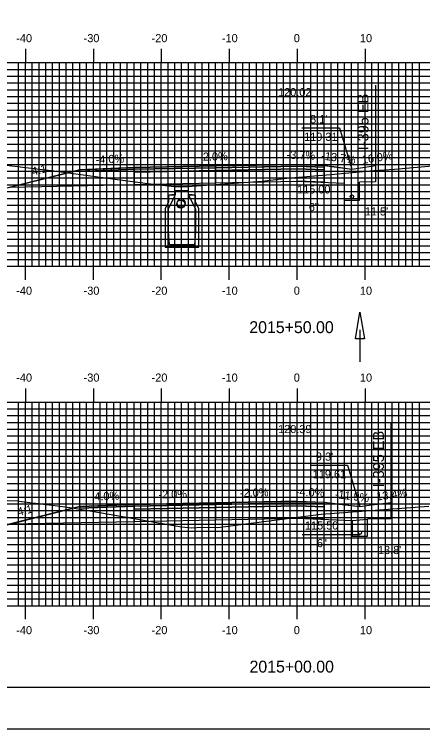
# Model space of a CAD drawing. Extents: x 854681 to 855024, y 366605 to 366825.
# Drawn here: x 854804.9 to 854865.1, y 366604.9 to 366710.2 of the extents above; entities that cross this region are included whole.
import ezdxf

# ---------------------------------------------------------------- set-up
doc = ezdxf.new("R2010")
doc.units = 0
for name, color, linetype in [('ANNOTATION', 7, 'Continuous'), ('BORDER', 7, 'Continuous'), ('D_Drainage_Ditch_Line', 7, 'Continuous'), ('D_Roadway_Centerline', 7, 'Continuous'), ('D_Roadway_Centerline_Text', 7, 'Continuous'), ('D_Roadway_Edge_Shoulder', 7, 'Continuous'), ('D_Roadway_Edge_TW', 7, 'Continuous'), ('D_Roadway_Pavement', 7, 'Continuous'), ('D_Roadway_SlopeLines', 7, 'Continuous'), ('D_Roadway_SubGrade', 7, 'Continuous'), ('D_Text_Standard', 7, 'Continuous'), ('H_V ANNOTATION', 7, 'Continuous'), ('JUNK', 7, 'Continuous'), ('MAJOR', 7, 'Continuous'), ('MINOR', 7, 'Continuous'), ('PDRAIN', 7, 'Continuous'), ('PLOT BOUNDARY', 7, 'Continuous'), ('S_Drainage_CB', 7, 'Continuous'), ('S_Drainage_Invert', 7, 'Continuous'), ('S_Roadway_Centerline', 7, 'Continuous')]:
    doc.layers.add(name, color=color, linetype=linetype)

msp = doc.modelspace()

# ---------------------------------------------------------------- linework, layer by layer
at = {"layer": 'ANNOTATION'}
for points in [[(854847.23, 366693.45), (854852.81, 366693.45), (854854.63, 366687.37)], [(854848.61, 366643.75), (854853.99, 366643.75), (854855.81, 366637.66)]]:
    msp.add_lwpolyline(points, dxfattribs=at)
at = {"layer": 'BORDER'}
msp.add_lwpolyline([(854696.96, 366611.06), (855016.96, 366611.06), (855016.96, 366821.06), (854696.96, 366821.06)], close=True, dxfattribs=at)
at = {"layer": 'D_Drainage_Ditch_Line'}
msp.add_line((854855.81, 366663.69), (854855.81, 366658.99), dxfattribs=at)
msp.add_lwpolyline([(854856.46, 366662.37), (854855.15, 366662.37), (854855.81, 366666.31)], close=True, dxfattribs=at)
at = {"layer": 'D_Roadway_Centerline'}
for p, q in [((854846.56, 366685.57), (854853.5, 366685.32)), ((854858.08, 366685.48), (854855.75, 366685.43)), ((854846.56, 366635.95), (854854.68, 366635.62))]:
    msp.add_line(p, q, dxfattribs=at)
for points in [[(854751.25, 366686.43), (854751.26, 366686.43), (854800.38, 366683.73), (854802.76, 366684.32), (854803.66, 366684.55), (854810.24, 366686.2), (854814.56, 366687.27), (854816.02, 366687.33), (854822.55, 366687.59), (854822.56, 366687.59), (854822.56, 366687.59), (854834.56, 366687.83), (854846.56, 366688.07), (854848.89, 366687.99), (854850.56, 366687.92), (854851.62, 366687.78), (854854.63, 366687.37)], [(854850.56, 366687.92), (854854.63, 366687.37)], [(854854.63, 366687.37), (854855.6, 366687.52), (854858.08, 366687.92)], [(854759.48, 366637.54), (854759.49, 366637.54), (854800.38, 366634.1), (854803.66, 366634.92), (854803.66, 366634.92), (854814.56, 366637.65), (854814.56, 366637.65), (854818.67, 366637.81), (854822.56, 366637.97), (854834.55, 366638.21), (854834.56, 366638.21), (854846.55, 366638.45), (854846.56, 366638.45), (854850.56, 366638.29), (854852.3, 366638.08), (854855.81, 366637.66)], [(854850.56, 366638.29), (854855.81, 366637.66)], [(854855.81, 366637.66), (854857.18, 366637.85), (854860.36, 366638.27)], [(854860.36, 366635.85), (854856.93, 366635.78)]]:
    msp.add_lwpolyline(points, dxfattribs=at)
at = {"layer": 'D_Roadway_Edge_Shoulder'}
for points in [[(854846.56, 366688.07), (854850.56, 366687.92), (854850.56, 366687.67), (854846.56, 366687.82)], [(854822.56, 366687.59), (854814.56, 366687.27), (854814.56, 366687.02), (854822.56, 366687.34)], [(854846.56, 366638.45), (854850.56, 366638.29), (854850.56, 366638.04), (854846.56, 366638.2)], [(854822.56, 366637.97), (854814.56, 366637.65), (854814.56, 366637.4), (854822.56, 366637.72)]]:
    msp.add_lwpolyline(points, close=True, dxfattribs=at)
at = {"layer": 'D_Roadway_Edge_TW'}
for points in [[(854834.56, 366687.83), (854822.56, 366687.59), (854822.56, 366687.34), (854834.56, 366687.58)], [(854846.56, 366688.07), (854834.56, 366687.83), (854834.56, 366687.58), (854846.56, 366687.82)], [(854846.56, 366638.45), (854834.56, 366638.21), (854834.56, 366637.96), (854846.56, 366638.2)], [(854834.56, 366638.21), (854822.56, 366637.97), (854822.56, 366637.72), (854834.56, 366637.96)]]:
    msp.add_lwpolyline(points, close=True, dxfattribs=at)
at = {"layer": 'D_Roadway_Pavement'}
for points in [[(854846.56, 366687.82), (854834.56, 366687.58), (854834.56, 366687.17), (854846.56, 366687.41)], [(854846.56, 366687.82), (854850.56, 366687.67), (854850.56, 366687.26), (854846.56, 366687.41)], [(854834.56, 366687.58), (854822.56, 366687.34), (854822.56, 366686.93), (854834.56, 366687.17)], [(854834.56, 366637.96), (854822.56, 366637.72), (854822.56, 366637.3), (854834.56, 366637.54)], [(854846.56, 366638.2), (854834.56, 366637.96), (854834.56, 366637.54), (854846.56, 366637.78)], [(854846.56, 366638.2), (854850.56, 366638.04), (854850.56, 366637.62), (854846.56, 366637.78)]]:
    msp.add_lwpolyline(points, close=True, dxfattribs=at)
for points in [[(854822.56, 366687.34), (854822.56, 366686.93)], [(854822.56, 366687.34), (854822.56, 366686.93)], [(854834.56, 366687.58), (854834.56, 366687.17)], [(854822.56, 366637.72), (854822.56, 366637.3)], [(854822.56, 366637.72), (854822.56, 366637.3)], [(854834.56, 366637.96), (854834.56, 366637.54)]]:
    msp.add_lwpolyline(points, dxfattribs=at)
at = {"layer": 'D_Roadway_SlopeLines'}
for p, q in [((854814.56, 366687.27), (854800.38, 366683.73)), ((854814.56, 366637.65), (854800.38, 366634.1))]:
    msp.add_line(p, q, dxfattribs=at)
at = {"layer": 'D_Roadway_SubGrade'}
for p, q in [((854858.08, 366699.73), (854858.08, 366685.48)), ((854860.36, 366650.08), (854860.36, 366635.85))]:
    msp.add_line(p, q, dxfattribs=at)
for points in [[(854846.56, 366687.41), (854850.56, 366687.26), (854850.56, 366687.67), (854850.56, 366687.92), (854850.56, 366685.42), (854846.56, 366685.57)], [(854822.56, 366686.93), (854822.56, 366687.34), (854814.56, 366687.02), (854814.56, 366687.27), (854804.38, 366684.73), (854822.56, 366685.09)], [(854834.56, 366687.17), (854822.56, 366686.93), (854822.56, 366685.09), (854834.56, 366685.33)], [(854846.56, 366687.41), (854834.56, 366687.17), (854834.56, 366685.33), (854846.56, 366685.57)], [(854822.56, 366637.3), (854822.56, 366637.72), (854814.56, 366637.4), (854814.56, 366637.65), (854804.38, 366635.1), (854822.56, 366635.47)], [(854834.56, 366637.54), (854822.56, 366637.3), (854822.56, 366635.47), (854834.56, 366635.71)], [(854846.56, 366637.78), (854834.56, 366637.54), (854834.56, 366635.71), (854846.56, 366635.95)], [(854846.56, 366637.78), (854850.56, 366637.62), (854850.56, 366638.04), (854850.56, 366638.29), (854850.56, 366635.79), (854846.56, 366635.95)]]:
    msp.add_lwpolyline(points, close=True, dxfattribs=at)
at = {"layer": 'JUNK'}
msp.add_line((854854.68, 366635.62), (854856.93, 366635.78), dxfattribs=at)
at = {"layer": 'MAJOR'}
for p, q in [((854806.56, 366705.06), (854806.56, 366703.06)), ((854816.56, 366705.06), (854816.56, 366703.06)), ((854826.56, 366705.06), (854826.56, 366703.06)), ((854836.56, 366705.06), (854836.56, 366703.06)), ((854846.56, 366705.06), (854846.56, 366703.06)), ((854856.56, 366705.06), (854856.56, 366703.06)), ((854706.56, 366703.06), (854986.56, 366703.06)), ((854706.56, 366703.06), (854986.56, 366703.06)), ((854806.56, 366673.06), (854806.56, 366703.06)), ((854816.56, 366673.06), (854816.56, 366703.06)), ((854826.56, 366673.06), (854826.56, 366703.06)), ((854836.56, 366673.06), (854836.56, 366703.06)), ((854846.56, 366673.06), (854846.56, 366703.06)), ((854856.56, 366673.06), (854856.56, 366703.06)), ((854706.56, 366698.06), (854986.56, 366698.06)), ((854706.56, 366693.06), (854986.56, 366693.06)), ((854706.56, 366688.06), (854986.56, 366688.06)), ((854706.56, 366683.06), (854986.56, 366683.06)), ((854706.56, 366678.06), (854986.56, 366678.06)), ((854706.56, 366673.06), (854986.56, 366673.06)), ((854706.56, 366673.06), (854986.56, 366673.06)), ((854806.56, 366671.05), (854806.56, 366673.06)), ((854816.56, 366671.05), (854816.56, 366673.06)), ((854826.56, 366671.05), (854826.56, 366673.06)), ((854836.56, 366671.05), (854836.56, 366673.06)), ((854846.56, 366671.05), (854846.56, 366673.06)), ((854856.56, 366671.05), (854856.56, 366673.06)), ((854806.56, 366655.06), (854806.56, 366653.06)), ((854816.56, 366655.06), (854816.56, 366653.06)), ((854826.56, 366655.06), (854826.56, 366653.06)), ((854836.56, 366655.06), (854836.56, 366653.06)), ((854846.56, 366655.06), (854846.56, 366653.06)), ((854856.56, 366655.06), (854856.56, 366653.06)), ((854706.56, 366653.06), (854986.56, 366653.06)), ((854706.56, 366653.06), (854986.56, 366653.06)), ((854806.56, 366623.06), (854806.56, 366653.06)), ((854816.56, 366623.06), (854816.56, 366653.06)), ((854826.56, 366623.06), (854826.56, 366653.06)), ((854836.56, 366623.06), (854836.56, 366653.06)), ((854846.56, 366623.06), (854846.56, 366653.06)), ((854856.56, 366623.06), (854856.56, 366653.06)), ((854706.56, 366648.06), (854986.56, 366648.06)), ((854706.56, 366643.06), (854986.56, 366643.06)), ((854706.56, 366638.06), (854986.56, 366638.06)), ((854706.56, 366633.06), (854986.56, 366633.06)), ((854706.56, 366628.06), (854986.56, 366628.06)), ((854706.56, 366623.06), (854986.56, 366623.06)), ((854706.56, 366623.06), (854986.56, 366623.06)), ((854806.56, 366621.05), (854806.56, 366623.06)), ((854816.56, 366621.05), (854816.56, 366623.06)), ((854826.56, 366621.05), (854826.56, 366623.06)), ((854836.56, 366621.05), (854836.56, 366623.06)), ((854846.56, 366621.05), (854846.56, 366623.06)), ((854856.56, 366621.05), (854856.56, 366623.06))]:
    msp.add_line(p, q, dxfattribs=at)
at = {"layer": 'MINOR'}
for p, q in [((854805.56, 366673.06), (854805.56, 366703.06)), ((854807.56, 366673.06), (854807.56, 366703.06)), ((854808.56, 366673.06), (854808.56, 366703.06)), ((854809.56, 366673.06), (854809.56, 366703.06)), ((854810.56, 366673.06), (854810.56, 366703.06)), ((854811.56, 366673.06), (854811.56, 366703.06)), ((854812.56, 366673.06), (854812.56, 366703.06)), ((854813.56, 366673.06), (854813.56, 366703.06)), ((854814.56, 366673.06), (854814.56, 366703.06)), ((854815.56, 366673.06), (854815.56, 366703.06)), ((854817.56, 366673.06), (854817.56, 366703.06)), ((854818.56, 366673.06), (854818.56, 366703.06)), ((854819.56, 366673.06), (854819.56, 366703.06)), ((854820.56, 366673.06), (854820.56, 366703.06)), ((854821.56, 366673.06), (854821.56, 366703.06)), ((854822.56, 366673.06), (854822.56, 366703.06)), ((854823.56, 366673.06), (854823.56, 366703.06)), ((854824.56, 366673.06), (854824.56, 366703.06)), ((854825.56, 366673.06), (854825.56, 366703.06)), ((854827.56, 366673.06), (854827.56, 366703.06)), ((854828.56, 366673.06), (854828.56, 366703.06)), ((854829.56, 366673.06), (854829.56, 366703.06)), ((854830.56, 366673.06), (854830.56, 366703.06)), ((854831.56, 366673.06), (854831.56, 366703.06)), ((854832.56, 366673.06), (854832.56, 366703.06)), ((854833.56, 366673.06), (854833.56, 366703.06)), ((854834.56, 366673.06), (854834.56, 366703.06)), ((854835.56, 366673.06), (854835.56, 366703.06)), ((854837.56, 366673.06), (854837.56, 366703.06)), ((854838.56, 366673.06), (854838.56, 366703.06)), ((854839.56, 366673.06), (854839.56, 366703.06)), ((854840.56, 366673.06), (854840.56, 366703.06)), ((854841.56, 366673.06), (854841.56, 366703.06)), ((854842.56, 366673.06), (854842.56, 366703.06)), ((854843.56, 366673.06), (854843.56, 366703.06)), ((854844.56, 366673.06), (854844.56, 366703.06)), ((854845.56, 366673.06), (854845.56, 366703.06)), ((854847.56, 366673.06), (854847.56, 366703.06)), ((854848.56, 366673.06), (854848.56, 366703.06)), ((854849.56, 366673.06), (854849.56, 366703.06)), ((854850.56, 366673.06), (854850.56, 366703.06)), ((854851.56, 366673.06), (854851.56, 366703.06)), ((854852.56, 366673.06), (854852.56, 366703.06)), ((854853.56, 366673.06), (854853.56, 366703.06)), ((854854.56, 366673.06), (854854.56, 366703.06)), ((854855.56, 366673.06), (854855.56, 366703.06)), ((854857.56, 366673.06), (854857.56, 366703.06)), ((854858.56, 366673.06), (854858.56, 366703.06)), ((854859.56, 366673.06), (854859.56, 366703.06)), ((854860.56, 366673.06), (854860.56, 366703.06)), ((854861.56, 366673.06), (854861.56, 366703.06)), ((854862.56, 366673.06), (854862.56, 366703.06)), ((854863.56, 366673.06), (854863.56, 366703.06)), ((854864.56, 366673.06), (854864.56, 366703.06)), ((854706.56, 366702.06), (854986.56, 366702.06)), ((854706.56, 366701.06), (854986.56, 366701.06)), ((854706.56, 366700.06), (854986.56, 366700.06)), ((854706.56, 366699.06), (854986.56, 366699.06)), ((854706.56, 366697.06), (854986.56, 366697.06)), ((854706.56, 366696.06), (854986.56, 366696.06)), ((854706.56, 366695.06), (854986.56, 366695.06)), ((854706.56, 366694.06), (854986.56, 366694.06)), ((854706.56, 366692.06), (854986.56, 366692.06)), ((854706.56, 366691.06), (854986.56, 366691.06)), ((854706.56, 366690.06), (854986.56, 366690.06)), ((854706.56, 366689.06), (854986.56, 366689.06)), ((854706.56, 366687.06), (854986.56, 366687.06)), ((854706.56, 366686.06), (854986.56, 366686.06)), ((854706.56, 366685.06), (854986.56, 366685.06)), ((854706.56, 366684.06), (854986.56, 366684.06)), ((854706.56, 366682.06), (854986.56, 366682.06)), ((854706.56, 366681.06), (854986.56, 366681.06)), ((854706.56, 366680.06), (854986.56, 366680.06)), ((854706.56, 366679.06), (854986.56, 366679.06)), ((854706.56, 366677.06), (854986.56, 366677.06)), ((854706.56, 366676.06), (854986.56, 366676.06)), ((854706.56, 366675.06), (854986.56, 366675.06)), ((854706.56, 366674.06), (854986.56, 366674.06)), ((854805.56, 366623.06), (854805.56, 366653.06)), ((854807.56, 366623.06), (854807.56, 366653.06)), ((854808.56, 366623.06), (854808.56, 366653.06)), ((854809.56, 366623.06), (854809.56, 366653.06)), ((854810.56, 366623.06), (854810.56, 366653.06)), ((854811.56, 366623.06), (854811.56, 366653.06)), ((854812.56, 366623.06), (854812.56, 366653.06)), ((854813.56, 366623.06), (854813.56, 366653.06)), ((854814.56, 366623.06), (854814.56, 366653.06)), ((854815.56, 366623.06), (854815.56, 366653.06)), ((854817.56, 366623.06), (854817.56, 366653.06)), ((854818.56, 366623.06), (854818.56, 366653.06)), ((854819.56, 366623.06), (854819.56, 366653.06)), ((854820.56, 366623.06), (854820.56, 366653.06)), ((854821.56, 366623.06), (854821.56, 366653.06)), ((854822.56, 366623.06), (854822.56, 366653.06)), ((854823.56, 366623.06), (854823.56, 366653.06)), ((854824.56, 366623.06), (854824.56, 366653.06)), ((854825.56, 366623.06), (854825.56, 366653.06)), ((854827.56, 366623.06), (854827.56, 366653.06)), ((854828.56, 366623.06), (854828.56, 366653.06)), ((854829.56, 366623.06), (854829.56, 366653.06)), ((854830.56, 366623.06), (854830.56, 366653.06)), ((854831.56, 366623.06), (854831.56, 366653.06)), ((854832.56, 366623.06), (854832.56, 366653.06)), ((854833.56, 366623.06), (854833.56, 366653.06)), ((854834.56, 366623.06), (854834.56, 366653.06)), ((854835.56, 366623.06), (854835.56, 366653.06)), ((854837.56, 366623.06), (854837.56, 366653.06)), ((854838.56, 366623.06), (854838.56, 366653.06)), ((854839.56, 366623.06), (854839.56, 366653.06)), ((854840.56, 366623.06), (854840.56, 366653.06)), ((854841.56, 366623.06), (854841.56, 366653.06)), ((854842.56, 366623.06), (854842.56, 366653.06)), ((854843.56, 366623.06), (854843.56, 366653.06)), ((854844.56, 366623.06), (854844.56, 366653.06)), ((854845.56, 366623.06), (854845.56, 366653.06)), ((854847.56, 366623.06), (854847.56, 366653.06)), ((854848.56, 366623.06), (854848.56, 366653.06)), ((854849.56, 366623.06), (854849.56, 366653.06)), ((854850.56, 366623.06), (854850.56, 366653.06)), ((854851.56, 366623.06), (854851.56, 366653.06)), ((854852.56, 366623.06), (854852.56, 366653.06)), ((854853.56, 366623.06), (854853.56, 366653.06)), ((854854.56, 366623.06), (854854.56, 366653.06)), ((854855.56, 366623.06), (854855.56, 366653.06)), ((854857.56, 366623.06), (854857.56, 366653.06)), ((854858.56, 366623.06), (854858.56, 366653.06)), ((854859.56, 366623.06), (854859.56, 366653.06)), ((854860.56, 366623.06), (854860.56, 366653.06)), ((854861.56, 366623.06), (854861.56, 366653.06)), ((854862.56, 366623.06), (854862.56, 366653.06)), ((854863.56, 366623.06), (854863.56, 366653.06)), ((854864.56, 366623.06), (854864.56, 366653.06)), ((854706.56, 366652.06), (854986.56, 366652.06)), ((854706.56, 366651.06), (854986.56, 366651.06)), ((854706.56, 366650.06), (854986.56, 366650.06)), ((854706.56, 366649.06), (854986.56, 366649.06)), ((854706.56, 366647.06), (854986.56, 366647.06)), ((854706.56, 366646.06), (854986.56, 366646.06)), ((854706.56, 366645.06), (854986.56, 366645.06)), ((854706.56, 366644.06), (854986.56, 366644.06)), ((854706.56, 366642.06), (854986.56, 366642.06)), ((854706.56, 366641.06), (854986.56, 366641.06)), ((854706.56, 366640.06), (854986.56, 366640.06)), ((854706.56, 366639.06), (854986.56, 366639.06)), ((854706.56, 366637.06), (854986.56, 366637.06)), ((854706.56, 366636.06), (854986.56, 366636.06)), ((854706.56, 366635.06), (854986.56, 366635.06)), ((854706.56, 366634.06), (854986.56, 366634.06)), ((854706.56, 366632.06), (854986.56, 366632.06)), ((854706.56, 366631.06), (854986.56, 366631.06)), ((854706.56, 366630.06), (854986.56, 366630.06)), ((854706.56, 366629.06), (854986.56, 366629.06)), ((854706.56, 366627.06), (854986.56, 366627.06)), ((854706.56, 366626.06), (854986.56, 366626.06)), ((854706.56, 366625.06), (854986.56, 366625.06)), ((854706.56, 366624.06), (854986.56, 366624.06))]:
    msp.add_line(p, q, dxfattribs=at)
at = {"layer": 'PDRAIN'}
for p, q in [((854846.13, 366683.06), (854854.63, 366683.06)), ((854847.31, 366633.56), (854855.81, 366633.56))]:
    msp.add_line(p, q, dxfattribs=at)
for points in [[(854853.5, 366685.32), (854853.5, 366682.81), (854855.75, 366682.81), (854855.75, 366685.43)], [(854854.68, 366635.62), (854854.68, 366633.31), (854856.93, 366633.31), (854856.93, 366635.78)]]:
    msp.add_lwpolyline(points, dxfattribs=at)
for centre in [(854854.63, 366683.31), (854855.81, 366633.81)]:
    msp.add_circle(centre, 0.25, dxfattribs=at)
at = {"layer": 'PLOT BOUNDARY'}
msp.add_lwpolyline([(854680.77, 366604.94), (855020.77, 366604.94), (855020.77, 366824.94), (854680.77, 366824.94)], close=True, dxfattribs=at)
at = {"layer": 'S_Drainage_CB'}
for p, q in [((854827.61, 366682.53), (854827.12, 366681.51)), ((854828.59, 366683.51), (854827.61, 366683.51)), ((854827.61, 366683.51), (854827.61, 366682.53)), ((854827.61, 366681.51), (854828.59, 366683.51)), ((854831.61, 366683.51), (854830.59, 366683.51)), ((854830.59, 366683.51), (854831.61, 366681.51)), ((854831.61, 366682.53), (854831.61, 366683.51)), ((854832.1, 366681.51), (854831.61, 366682.53)), ((854827.12, 366681.51), (854827.12, 366675.87)), ((854827.61, 366678.2), (854827.61, 366681.51)), ((854831.61, 366681.51), (854831.61, 366678.2)), ((854832.1, 366675.87), (854832.1, 366681.51)), ((854827.77, 366676.2), (854827.61, 366678.2)), ((854831.61, 366678.2), (854831.45, 366676.2)), ((854831.45, 366676.2), (854827.77, 366676.2)), ((854827.12, 366675.87), (854832.1, 366675.87))]:
    msp.add_line(p, q, dxfattribs=at)
msp.add_lwpolyline([(854831.09, 366683.56), (854830.59, 366683.56), (854830.59, 366684.18), (854828.59, 366684.18), (854828.59, 366683.56), (854828.1, 366683.56)], dxfattribs=at)
at = {"layer": 'S_Drainage_Invert'}
for centre in [(854829.43, 366682.2), (854829.48, 366682.38)]:
    msp.add_circle(centre, 0.6, dxfattribs=at)
at = {"layer": 'S_Roadway_Centerline'}
for points in [[(854802.48, 366688.08), (854805.78, 366687.71), (854810.76, 366687.09), (854820.1, 366685.84), (854824.6, 366685.27), (854828.47, 366684.81), (854830.42, 366684.82), (854841.39, 366685.61), (854845.07, 366686.03), (854852.06, 366686.62), (854857.87, 366687.17), (854860.89, 366687.37), (854867.04, 366687.9)], [(854800.73, 366638.67), (854805.37, 366638.49), (854805.99, 366638.4), (854811.27, 366637.79), (854813.43, 366637.48), (854817.77, 366636.74), (854829.55, 366634.68), (854830.95, 366634.51), (854832.59, 366634.63), (854834.88, 366634.59), (854840.15, 366635.28), (854850.08, 366636.54), (854865.93, 366637.73)]]:
    msp.add_lwpolyline(points, dxfattribs=at)

# ---------------------------------------------------------------- texts
at = {"layer": 'ANNOTATION'}
for s, height, rotation, p in [('I-395 EB', 1.6, 90, (854857.07, 366690.15)), ('-3.7%', 1.2, 357.8671, (854845, 366688.91)), ('16.0%', 1.2, 9.1001, (854856.19, 366688.12)), ('-4.0%', 1.2, 2.2905, (854816.92, 366688.17)), ('-2.0%', 1.2, 1.1458, (854832.16, 366688.59)), ('-13.7%', 1.2, 352.2075, (854850.05, 366688.8)), ('4:1', 1.2, 14.0381, (854807.64, 366686.41)), ('I-395 EB', 1.6, 90, (854859.34, 366640.5)), ('-4.0%', 1.2, 357.7098, (854846.35, 366639.26)), ('-4.0%', 1.2, 2.2907, (854816.19, 366638.51)), ('-2.0%', 1.2, 1.1458, (854826.16, 366638.84)), ('-2.0%', 1.2, 1.1458, (854838.16, 366639.08)), ('-11.9%', 1.2, 353.2245, (854852.05, 366638.92)), ('13.4%', 1.2, 7.659, (854858.32, 366638.53)), ('4:1', 1.2, 14.0381, (854805.53, 366636.26))]:
    msp.add_text(s, height=height, rotation=rotation, dxfattribs=at).set_placement(p)
for s, p in [("8.1' ", (854848.48, 366694.13)), ('119.31', (854847.6, 366691.53)), ('115.00', (854846.56, 366683.78)), ('6"', (854848.29, 366681.18)), ("9.3' ", (854849.33, 366644.42)), ('119.61', (854848.86, 366641.82)), ('115.50', (854847.72, 366634.28)), ('6"', (854849.47, 366631.68))]:
    msp.add_text(s, height=1.2, dxfattribs=at).set_placement(p)
at = {"layer": 'D_Roadway_Centerline_Text'}
for s, p in [('120.02', (854843.76, 366698.1)), ('120.39', (854843.76, 366648.48))]:
    msp.add_text(s, height=1.2, dxfattribs=at).set_placement(p)
at = {"layer": 'D_Text_Standard'}
for s, p in [("11.5'", (854856.53, 366680.54)), ("13.8'", (854858.47, 366630.66))]:
    msp.add_text(s, height=1.2, dxfattribs=at).set_placement(p)
at = {"layer": 'H_V ANNOTATION'}
for s, height, p in [('-40', 1.2, (854805.21, 366706.06)), ('-30', 1.2, (854815.13, 366706.06)), ('-20', 1.2, (854825.14, 366706.06)), ('-10', 1.2, (854835.49, 366706.06)), ('0', 1.2, (854846.07, 366706.06)), ('10', 1.2, (854855.81, 366706.06)), ('-40', 1.2, (854805.21, 366668.86)), ('-30', 1.2, (854815.13, 366668.86)), ('-20', 1.2, (854825.14, 366668.86)), ('-10', 1.2, (854835.49, 366668.86)), ('0', 1.2, (854846.07, 366668.86)), ('10', 1.2, (854855.81, 366668.86)), ('2015+50.00', 1.75, (854839.52, 366663.21)), ('-40', 1.2, (854805.21, 366656.06)), ('-30', 1.2, (854815.13, 366656.06)), ('-20', 1.2, (854825.14, 366656.06)), ('-10', 1.2, (854835.49, 366656.06)), ('0', 1.2, (854846.07, 366656.06)), ('10', 1.2, (854855.81, 366656.06)), ('-40', 1.2, (854805.21, 366618.86)), ('-30', 1.2, (854815.13, 366618.86)), ('-20', 1.2, (854825.14, 366618.86)), ('-10', 1.2, (854835.49, 366618.86)), ('0', 1.2, (854846.07, 366618.86)), ('10', 1.2, (854855.81, 366618.86)), ('2015+00.00', 1.75, (854839.55, 366613.21))]:
    msp.add_text(s, height=height, dxfattribs=at).set_placement(p)

doc.saveas('drawing.dxf')
